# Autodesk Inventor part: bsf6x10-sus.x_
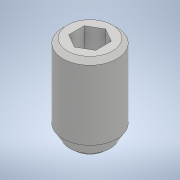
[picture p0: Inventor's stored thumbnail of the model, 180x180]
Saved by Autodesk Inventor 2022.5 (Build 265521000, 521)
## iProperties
Created: 2020-01
Part Number: bsf6x10-sus.x_
Material: 一般
Document SubType Name: Modeling
Designer: ImaoCorp
Density: 1 g/cm^3
Appearance: 既定
Sending System: SOLIDWORKS 2018-2018316
MC: AMD64
MC_MODEL: Intel64 Family 6 Model 60 Stepping 3, GenuineIntel
OS: Windows_NT
FRU: Parasolid Version 30.0, build 310,  6- 8-2018
FORMAT: text
GUISE: transmit
KEY: bsf6x10-sus
FILE: bsf6x10-sus.x_t
DATE: Thu Jan 23 16:48:34 2020
Author: ImaoCorp
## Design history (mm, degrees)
feature "Base1"
node "ソリッド1"
